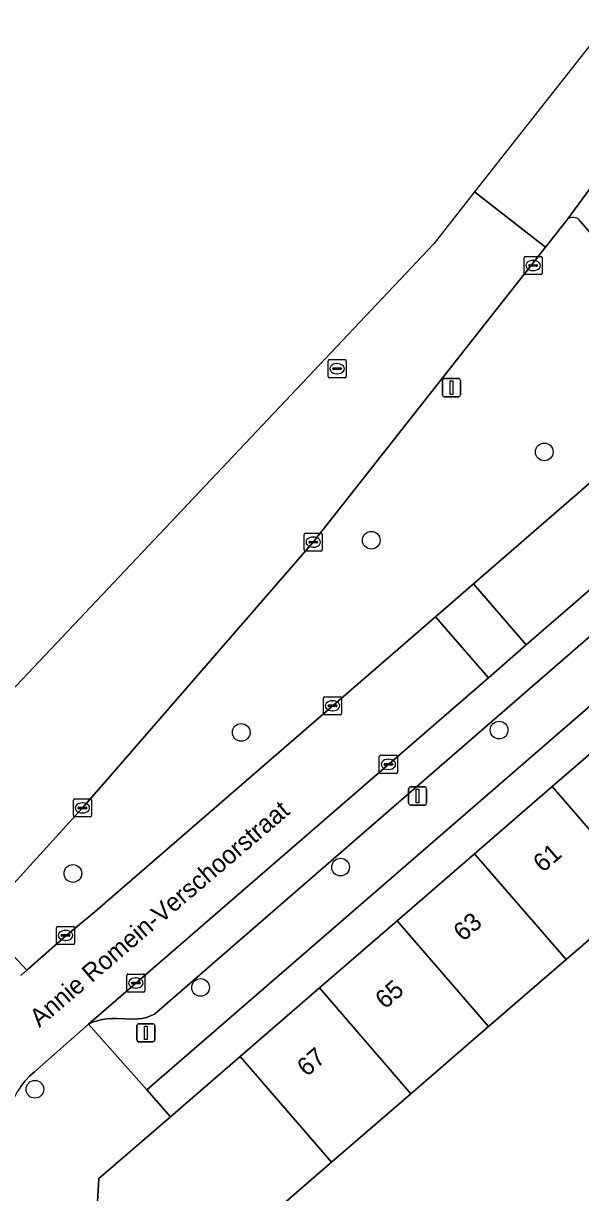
# Model space of a CAD drawing. Extents: x 160304 to 160955, y 383684 to 384161.
# Drawn here: x 160362.7 to 160393.5, y 384055.7 to 384120.3 of the extents above; entities that cross this region are included whole.
import ezdxf

# ---------------------------------------------------------------- set-up
doc = ezdxf.new("R2010")
doc.units = 0
for name, color, linetype in [('IMGEO_Berm_groen', 7, 'Continuous'), ('IMGEO_Boom', 7, 'Continuous'), ('IMGEO_Erf', 7, 'Continuous'), ('IMGEO_Kolk', 7, 'Continuous'), ('IMGEO_Lichtmast', 7, 'Continuous'), ('IMGEO_Openbare_ruimte_label', 7, 'Continuous'), ('IMGEO_Pand', 7, 'Continuous'), ('IMGEO_Pand_nummerreeks', 7, 'Continuous'), ('IMGEO_Parkeervlak_open', 7, 'Continuous'), ('IMGEO_Rijbaan_lokaal_gesloten', 7, 'Continuous'), ('IMGEO_Rijbaan_lokaal_open', 7, 'Continuous'), ('IMGEO_Rioolput', 7, 'Continuous'), ('IMGEO_Voetpad_open', 7, 'Continuous')]:
    doc.layers.add(name, color=color, linetype=linetype)

msp = doc.modelspace()

# ---------------------------------------------------------------- linework, layer by layer
at = {"layer": 'IMGEO_Berm_groen'}
for points in [[(160392.757, 384109.377), (160391.585, 384107.888), (160378.757, 384091.601), (160367.654, 384078.8), (160366.004, 384076.919), (160361.087, 384071.52), (160360.319, 384070.736), (160362.943, 384067.958), (160365.075, 384069.831), (160366.686, 384071.182), (160385.508, 384087.482)], [(160385.508, 384087.482), (160387.602, 384089.296), (160398.566, 384098.79), (160396.61, 384101.048), (160398.923, 384103.034), (160393.527, 384109.316)], [(160362.595, 384067.653), (160362.943, 384067.958), (160360.319, 384070.736), (160352.168, 384063.187), (160351.994, 384063.019), (160352.31, 384062.716), (160352.658, 384062.992), (160352.87, 384063.056)]]:
    msp.add_lwpolyline(points, dxfattribs=at)
msp.add_arc((160393.119, 384109.05), 0.487, 33.05714, 137.88375, dxfattribs=at)
at = {"layer": 'IMGEO_Boom'}
for centre in [(160391.521, 384096.582), (160381.964, 384091.704), (160374.777, 384081.092), (160389.026, 384081.218), (160365.479, 384073.297), (160380.264, 384073.648), (160372.531, 384067.002), (160363.383, 384061.375)]:
    msp.add_circle(centre, 0.489, dxfattribs=at)
at = {"layer": 'IMGEO_Erf'}
msp.add_lwpolyline([(160370.867, 384059.859), (160374.719, 384063.189), (160379.098, 384066.975), (160383.385, 384070.682), (160387.672, 384074.39), (160391.96, 384078.097), (160396.247, 384081.804), (160400.628, 384085.592), (160402.16, 384083.813), (160406.529, 384087.579), (160410.806, 384091.267), (160415.083, 384094.954), (160419.36, 384098.641), (160423.741, 384102.417), (160420.868, 384105.779), (160369.56, 384061.353)], close=True, dxfattribs=at)
msp.add_lwpolyline([(160397.013, 384072.253), (160392.724, 384068.546), (160388.436, 384064.84), (160384.148, 384061.134), (160379.769, 384057.349), (160375.75, 384053.876)], dxfattribs=at)
at = {"layer": 'IMGEO_Kolk'}
for p, q in [((160390.401, 384106.451), (160390.401, 384107.303)), ((160390.476, 384107.377), (160391.328, 384107.377)), ((160391.402, 384107.303), (160391.402, 384106.451)), ((160390.66, 384106.871), (160390.66, 384106.883)), ((160391.098, 384106.834), (160390.7, 384106.834)), ((160390.703, 384106.92), (160391.101, 384106.92)), ((160390.889, 384107.157), (160390.914, 384107.157)), ((160391.144, 384106.883), (160391.144, 384106.871)), ((160391.328, 384106.377), (160390.476, 384106.377)), ((160390.912, 384106.597), (160390.887, 384106.597)), ((160378.257, 384091.174), (160378.257, 384092.026)), ((160378.332, 384092.1), (160379.184, 384092.1)), ((160378.745, 384091.88), (160378.77, 384091.88)), ((160379.258, 384092.026), (160379.258, 384091.174)), ((160378.516, 384091.594), (160378.516, 384091.606)), ((160378.954, 384091.557), (160378.556, 384091.557)), ((160378.559, 384091.643), (160378.957, 384091.643)), ((160378.768, 384091.32), (160378.743, 384091.32)), ((160379, 384091.606), (160379, 384091.594)), ((160379.184, 384091.1), (160378.332, 384091.1)), ((160379.323, 384082.135), (160379.323, 384082.987)), ((160379.398, 384083.061), (160380.25, 384083.061)), ((160379.811, 384082.841), (160379.836, 384082.841)), ((160380.324, 384082.987), (160380.324, 384082.135)), ((160379.582, 384082.555), (160379.582, 384082.567)), ((160380.02, 384082.518), (160379.622, 384082.518)), ((160379.625, 384082.604), (160380.023, 384082.604)), ((160379.834, 384082.281), (160379.809, 384082.281)), ((160380.066, 384082.567), (160380.066, 384082.555)), ((160380.25, 384082.061), (160379.398, 384082.061)), ((160382.407, 384078.899), (160382.407, 384079.751)), ((160382.482, 384079.825), (160383.334, 384079.825)), ((160382.895, 384079.605), (160382.92, 384079.605)), ((160383.408, 384079.751), (160383.408, 384078.899)), ((160382.666, 384079.319), (160382.666, 384079.331)), ((160383.104, 384079.282), (160382.706, 384079.282)), ((160382.709, 384079.368), (160383.107, 384079.368)), ((160382.918, 384079.045), (160382.893, 384079.045)), ((160383.15, 384079.331), (160383.15, 384079.319)), ((160383.334, 384078.825), (160382.482, 384078.825)), ((160365.504, 384076.492), (160365.504, 384077.344)), ((160365.579, 384077.418), (160366.431, 384077.418)), ((160365.806, 384076.961), (160366.204, 384076.961)), ((160365.992, 384077.198), (160366.017, 384077.198)), ((160366.505, 384077.344), (160366.505, 384076.492)), ((160366.431, 384076.418), (160365.579, 384076.418)), ((160365.763, 384076.912), (160365.763, 384076.924)), ((160366.201, 384076.875), (160365.803, 384076.875)), ((160366.015, 384076.638), (160365.99, 384076.638)), ((160366.247, 384076.924), (160366.247, 384076.912)), ((160364.574, 384069.45), (160364.574, 384070.302)), ((160364.649, 384070.376), (160365.501, 384070.376)), ((160364.833, 384069.87), (160364.833, 384069.882)), ((160364.876, 384069.919), (160365.274, 384069.919)), ((160365.062, 384070.156), (160365.087, 384070.156)), ((160365.317, 384069.882), (160365.317, 384069.87)), ((160365.575, 384070.302), (160365.575, 384069.45)), ((160365.501, 384069.376), (160364.649, 384069.376)), ((160365.271, 384069.833), (160364.873, 384069.833)), ((160365.085, 384069.596), (160365.06, 384069.596)), ((160368.458, 384066.819), (160368.458, 384067.671)), ((160368.533, 384067.745), (160369.385, 384067.745)), ((160368.717, 384067.239), (160368.717, 384067.251)), ((160368.76, 384067.288), (160369.158, 384067.288)), ((160368.946, 384067.525), (160368.971, 384067.525)), ((160369.201, 384067.251), (160369.201, 384067.239)), ((160369.459, 384067.671), (160369.459, 384066.819)), ((160369.385, 384066.745), (160368.533, 384066.745)), ((160369.155, 384067.202), (160368.757, 384067.202)), ((160368.969, 384066.965), (160368.944, 384066.965))]:
    msp.add_line(p, q, dxfattribs=at)
for points in [[(160390.401, 384106.451), (160390.401, 384107.303)], [(160390.476, 384107.377), (160391.328, 384107.377)], [(160391.402, 384107.303), (160391.402, 384106.451)], [(160391.328, 384106.377), (160390.476, 384106.377)], [(160378.257, 384091.174), (160378.257, 384092.026)], [(160378.332, 384092.1), (160379.184, 384092.1)], [(160379.258, 384092.026), (160379.258, 384091.174)], [(160379.184, 384091.1), (160378.332, 384091.1)], [(160379.323, 384082.135), (160379.323, 384082.987)], [(160379.398, 384083.061), (160380.25, 384083.061)], [(160380.324, 384082.987), (160380.324, 384082.135)], [(160380.25, 384082.061), (160379.398, 384082.061)], [(160382.407, 384078.899), (160382.407, 384079.751)], [(160382.482, 384079.825), (160383.334, 384079.825)], [(160383.408, 384079.751), (160383.408, 384078.899)], [(160383.334, 384078.825), (160382.482, 384078.825)], [(160365.504, 384076.492), (160365.504, 384077.344)], [(160365.579, 384077.418), (160366.431, 384077.418)], [(160366.505, 384077.344), (160366.505, 384076.492)], [(160366.431, 384076.418), (160365.579, 384076.418)], [(160364.574, 384069.45), (160364.574, 384070.302)], [(160364.649, 384070.376), (160365.501, 384070.376)], [(160365.575, 384070.302), (160365.575, 384069.45)], [(160365.501, 384069.376), (160364.649, 384069.376)], [(160368.458, 384066.819), (160368.458, 384067.671)], [(160368.533, 384067.745), (160369.385, 384067.745)], [(160369.459, 384067.671), (160369.459, 384066.819)], [(160369.385, 384066.745), (160368.533, 384066.745)]]:
    msp.add_lwpolyline(points, dxfattribs=at)
for centre, radius, start, end in [((160390.478, 384107.301), 0.0765, 91.55205, 178.44795), ((160390.478, 384107.301), 0.0765, 91.55205, 178.44795), ((160391.326, 384107.301), 0.0765, 1.55205, 88.44795), ((160391.326, 384107.301), 0.0765, 1.55205, 88.44795), ((160390.7, 384106.88), 0.0403, 85.87752, 175.75265), ((160390.697, 384106.87), 0.0366, 178.93798, 274.71019), ((160391.101, 384106.877), 0.043, 264.86636, 352.45326), ((160391.105, 384106.882), 0.0386, 1.73085, 96.63898), ((160390.478, 384106.453), 0.0765, 181.55205, 268.44795), ((160390.478, 384106.453), 0.0765, 181.55205, 268.44795), ((160391.326, 384106.453), 0.0765, 271.55205, 358.44795), ((160391.326, 384106.453), 0.0765, 271.55205, 358.44795), ((160378.334, 384092.024), 0.0765, 91.55205, 178.44795), ((160378.334, 384092.024), 0.0765, 91.55205, 178.44795), ((160379.182, 384092.024), 0.0765, 1.55205, 88.44795), ((160379.182, 384092.024), 0.0765, 1.55205, 88.44795), ((160378.334, 384091.176), 0.0765, 181.55205, 268.44795), ((160378.334, 384091.176), 0.0765, 181.55205, 268.44795), ((160378.556, 384091.603), 0.0403, 85.87752, 175.75265), ((160378.553, 384091.593), 0.0366, 178.93798, 274.71019), ((160378.957, 384091.6), 0.043, 264.86636, 352.45326), ((160378.961, 384091.605), 0.0386, 1.73085, 96.63898), ((160379.182, 384091.176), 0.0765, 271.55205, 358.44795), ((160379.182, 384091.176), 0.0765, 271.55205, 358.44795), ((160379.4, 384082.985), 0.0765, 91.55205, 178.44795), ((160379.4, 384082.985), 0.0765, 91.55205, 178.44795), ((160380.248, 384082.985), 0.0765, 1.55205, 88.44795), ((160380.248, 384082.985), 0.0765, 1.55205, 88.44795), ((160379.4, 384082.137), 0.0765, 181.55205, 268.44795), ((160379.4, 384082.137), 0.0765, 181.55205, 268.44795), ((160379.622, 384082.564), 0.0403, 85.87752, 175.75265), ((160379.619, 384082.554), 0.0366, 178.93798, 274.71019), ((160380.023, 384082.561), 0.043, 264.86636, 352.45326), ((160380.027, 384082.566), 0.0386, 1.73085, 96.63898), ((160380.248, 384082.137), 0.0765, 271.55205, 358.44795), ((160380.248, 384082.137), 0.0765, 271.55205, 358.44795), ((160382.484, 384079.749), 0.0765, 91.55205, 178.44795), ((160382.484, 384079.749), 0.0765, 91.55205, 178.44795), ((160383.332, 384079.749), 0.0765, 1.55205, 88.44795), ((160383.332, 384079.749), 0.0765, 1.55205, 88.44795), ((160382.484, 384078.901), 0.0765, 181.55205, 268.44795), ((160382.484, 384078.901), 0.0765, 181.55205, 268.44795), ((160382.706, 384079.328), 0.0403, 85.87752, 175.75265), ((160382.703, 384079.318), 0.0366, 178.93798, 274.71019), ((160383.107, 384079.325), 0.043, 264.86636, 352.45326), ((160383.111, 384079.33), 0.0386, 1.73085, 96.63898), ((160383.332, 384078.901), 0.0765, 271.55205, 358.44795), ((160383.332, 384078.901), 0.0765, 271.55205, 358.44795), ((160365.581, 384077.342), 0.0765, 91.55205, 178.44795), ((160365.581, 384077.342), 0.0765, 91.55205, 178.44795), ((160365.803, 384076.921), 0.0403, 85.87752, 175.75265), ((160366.208, 384076.923), 0.0386, 1.73085, 96.63898), ((160366.429, 384077.342), 0.0765, 1.55205, 88.44795), ((160366.429, 384077.342), 0.0765, 1.55205, 88.44795), ((160365.581, 384076.494), 0.0765, 181.55205, 268.44795), ((160365.581, 384076.494), 0.0765, 181.55205, 268.44795), ((160365.8, 384076.911), 0.0366, 178.93798, 274.71019), ((160366.204, 384076.918), 0.043, 264.86636, 352.45326), ((160366.429, 384076.494), 0.0765, 271.55205, 358.44795), ((160366.429, 384076.494), 0.0765, 271.55205, 358.44795), ((160364.651, 384070.3), 0.0765, 91.55205, 178.44795), ((160364.651, 384070.3), 0.0765, 91.55205, 178.44795), ((160364.873, 384069.879), 0.0403, 85.87752, 175.75265), ((160364.87, 384069.869), 0.0366, 178.93798, 274.71019), ((160365.274, 384069.876), 0.043, 264.86636, 352.45326), ((160365.278, 384069.881), 0.0386, 1.73085, 96.63898), ((160365.499, 384070.3), 0.0765, 1.55205, 88.44795), ((160365.499, 384070.3), 0.0765, 1.55205, 88.44795), ((160364.651, 384069.452), 0.0765, 181.55205, 268.44795), ((160364.651, 384069.452), 0.0765, 181.55205, 268.44795), ((160365.499, 384069.452), 0.0765, 271.55205, 358.44795), ((160365.499, 384069.452), 0.0765, 271.55205, 358.44795), ((160368.535, 384067.669), 0.0765, 91.55205, 178.44795), ((160368.535, 384067.669), 0.0765, 91.55205, 178.44795), ((160368.757, 384067.248), 0.0403, 85.87752, 175.75265), ((160369.162, 384067.25), 0.0386, 1.73085, 96.63898), ((160369.383, 384067.669), 0.0765, 1.55205, 88.44795), ((160369.383, 384067.669), 0.0765, 1.55205, 88.44795), ((160368.535, 384066.821), 0.0765, 181.55205, 268.44795), ((160368.535, 384066.821), 0.0765, 181.55205, 268.44795), ((160368.754, 384067.238), 0.0366, 178.93798, 274.71019), ((160369.158, 384067.245), 0.043, 264.86636, 352.45326), ((160369.383, 384066.821), 0.0765, 271.55205, 358.44795), ((160369.383, 384066.821), 0.0765, 271.55205, 358.44795)]:
    msp.add_arc(centre, radius, start, end, dxfattribs=at)
for centre, major_axis, ratio, start_param, end_param in [((160390.888, 384106.877), (-0.387, 0.002), 0.722429, 4.712389, 7.853982), ((160390.913, 384106.877), (-0.39, 0.002), 0.717154, 1.570796, 4.712389), ((160378.744, 384091.6), (-0.387, 0.002), 0.722429, 4.712389, 7.853982), ((160378.769, 384091.6), (-0.39, 0.002), 0.717154, 1.570796, 4.712389), ((160379.81, 384082.561), (-0.387, 0.002), 0.722429, 4.712389, 7.853982), ((160379.835, 384082.561), (-0.39, 0.002), 0.717154, 1.570796, 4.712389), ((160382.894, 384079.325), (-0.387, 0.002), 0.722429, 4.712389, 7.853982), ((160382.919, 384079.325), (-0.39, 0.002), 0.717154, 1.570796, 4.712389), ((160365.991, 384076.918), (-0.387, 0.002), 0.722429, 4.712389, 7.853982), ((160366.016, 384076.918), (-0.39, 0.002), 0.717154, 1.570796, 4.712389), ((160365.061, 384069.876), (-0.387, 0.002), 0.722429, 4.712389, 7.853982), ((160365.086, 384069.876), (-0.39, 0.002), 0.717154, 1.570796, 4.712389), ((160368.945, 384067.245), (-0.387, 0.002), 0.722429, 4.712389, 7.853982), ((160368.97, 384067.245), (-0.39, 0.002), 0.717154, 1.570796, 4.712389)]:
    msp.add_ellipse(centre, major_axis=major_axis, ratio=ratio, start_param=start_param, end_param=end_param, dxfattribs=at)
at = {"layer": 'IMGEO_Lichtmast'}
for p, q in [((160385.895, 384099.733), (160385.895, 384100.533)), ((160385.895, 384100.533), (160385.895, 384099.733)), ((160385.995, 384100.633), (160386.785, 384100.633)), ((160386.785, 384100.633), (160385.995, 384100.633)), ((160386.885, 384100.533), (160386.885, 384099.733)), ((160386.885, 384099.733), (160386.885, 384100.533)), ((160386.785, 384099.633), (160385.995, 384099.633)), ((160385.995, 384099.633), (160386.785, 384099.633)), ((160384.025, 384077.175), (160384.025, 384077.975)), ((160384.025, 384077.975), (160384.025, 384077.175)), ((160384.125, 384078.075), (160384.915, 384078.075)), ((160384.915, 384078.075), (160384.125, 384078.075)), ((160385.015, 384077.975), (160385.015, 384077.175)), ((160385.015, 384077.175), (160385.015, 384077.975)), ((160384.915, 384077.075), (160384.125, 384077.075)), ((160384.125, 384077.075), (160384.915, 384077.075)), ((160369.012, 384064.097), (160369.012, 384064.897)), ((160369.012, 384064.897), (160369.012, 384064.097)), ((160369.112, 384064.997), (160369.902, 384064.997)), ((160369.902, 384064.997), (160369.112, 384064.997)), ((160370.002, 384064.897), (160370.002, 384064.097)), ((160370.002, 384064.097), (160370.002, 384064.897)), ((160369.902, 384063.997), (160369.112, 384063.997)), ((160369.112, 384063.997), (160369.902, 384063.997))]:
    msp.add_line(p, q, dxfattribs=at)
for points in [[(160386.315, 384100.508), (160386.465, 384100.508), (160386.465, 384099.758), (160386.315, 384099.758), (160386.315, 384100.508)], [(160384.445, 384077.95), (160384.595, 384077.95), (160384.595, 384077.2), (160384.445, 384077.2), (160384.445, 384077.95)], [(160369.432, 384064.872), (160369.582, 384064.872), (160369.582, 384064.122), (160369.432, 384064.122), (160369.432, 384064.872)]]:
    msp.add_lwpolyline(points, dxfattribs=at)
for centre, start, end in [((160385.995, 384100.533), 90, 180), ((160385.995, 384100.533), 90, 180), ((160386.785, 384100.533), 0, 90), ((160386.785, 384100.533), 360, 90), ((160385.995, 384099.733), 180, 270), ((160385.995, 384099.733), 180, 270), ((160386.785, 384099.733), 270, 0), ((160386.785, 384099.733), 270, 0), ((160384.125, 384077.975), 90, 180), ((160384.125, 384077.975), 90, 180), ((160384.915, 384077.975), 0, 90), ((160384.915, 384077.975), 360, 90), ((160384.125, 384077.175), 180, 270), ((160384.125, 384077.175), 180, 270), ((160384.915, 384077.175), 270, 0), ((160384.915, 384077.175), 270, 0), ((160369.112, 384064.897), 90, 180), ((160369.112, 384064.897), 90, 180), ((160369.902, 384064.897), 0, 90), ((160369.902, 384064.897), 360, 90), ((160369.112, 384064.097), 180, 270), ((160369.112, 384064.097), 180, 270), ((160369.902, 384064.097), 270, 0), ((160369.902, 384064.097), 270, 0)]:
    msp.add_arc(centre, 0.1, start, end, dxfattribs=at)
at = {"layer": 'IMGEO_Pand'}
for points in [[(160391.96, 384078.097), (160397.013, 384072.253), (160401.301, 384075.959), (160396.247, 384081.804)], [(160391.96, 384078.097), (160387.672, 384074.39), (160392.724, 384068.546), (160397.013, 384072.253)], [(160383.385, 384070.682), (160388.436, 384064.84), (160392.724, 384068.546), (160387.672, 384074.39)], [(160379.098, 384066.975), (160384.148, 384061.134), (160388.436, 384064.84), (160383.385, 384070.682)], [(160379.098, 384066.975), (160374.719, 384063.189), (160379.769, 384057.349), (160384.148, 384061.134)], [(160379.769, 384057.349), (160374.719, 384063.189), (160370.867, 384059.859), (160366.918, 384056.444), (160366.832, 384055.157), (160366.712, 384053.361), (160366.625, 384052.063), (160369.22, 384049.062), (160373.455, 384044.164), (160379.304, 384049.215), (160375.721, 384053.359), (160375.75, 384053.876)]]:
    msp.add_lwpolyline(points, close=True, dxfattribs=at)
at = {"layer": 'IMGEO_Parkeervlak_open'}
msp.add_lwpolyline([(160399.384, 384093.594), (160390.525, 384085.922), (160388.431, 384084.109), (160366.337, 384064.976), (160366.57, 384065.079), (160366.829, 384065.167), (160367.094, 384065.232), (160367.365, 384065.273), (160367.638, 384065.29), (160367.912, 384065.282), (160368.819, 384065.249), (160369.062, 384065.261), (160369.302, 384065.296), (160369.539, 384065.351), (160369.77, 384065.428), (160369.98, 384065.518), (160413.547, 384103.317)], dxfattribs=at)
at = {"layer": 'IMGEO_Rijbaan_lokaal_gesloten'}
msp.add_lwpolyline([(160394.994, 384120.252), (160387.672, 384110.946), (160391.585, 384107.888), (160392.757, 384109.377), (160395.112, 384112.569), (160397.736, 384115.959), (160398.679, 384117.35)], close=True, dxfattribs=at)
for points in [[(160387.672, 384110.946), (160385.413, 384108.074), (160347.496, 384067.978), (160304.005, 384030.821)], [(160327.338, 384042.569), (160343.612, 384055.892), (160351.994, 384063.019), (160352.168, 384063.187), (160360.319, 384070.736), (160361.087, 384071.52), (160366.004, 384076.919), (160367.654, 384078.8), (160378.757, 384091.601), (160391.585, 384107.888), (160387.672, 384110.946)]]:
    msp.add_lwpolyline(points, dxfattribs=at)
at = {"layer": 'IMGEO_Rijbaan_lokaal_open'}
for points in [[(160412.264, 384110.636), (160403.163, 384102.78), (160400.861, 384100.778), (160398.566, 384098.79), (160387.602, 384089.296), (160390.525, 384085.922), (160399.384, 384093.594), (160414.316, 384106.549)], [(160362.604, 384061.536), (160362.831, 384061.826), (160363.083, 384062.094), (160363.357, 384062.338), (160366.337, 384064.976), (160388.431, 384084.109), (160385.508, 384087.482), (160366.686, 384071.182), (160365.075, 384069.831), (160362.943, 384067.958), (160362.595, 384067.653)]]:
    msp.add_lwpolyline(points, dxfattribs=at)
msp.add_lwpolyline([(160388.431, 384084.109), (160390.525, 384085.922), (160387.602, 384089.296), (160385.508, 384087.482)], close=True, dxfattribs=at)
at = {"layer": 'IMGEO_Rioolput'}
for p, q in [((160379.574, 384100.752), (160379.574, 384101.604)), ((160379.649, 384101.678), (160380.501, 384101.678)), ((160380.575, 384101.604), (160380.575, 384100.752)), ((160379.833, 384101.172), (160379.833, 384101.184)), ((160380.271, 384101.135), (160379.873, 384101.135)), ((160379.876, 384101.221), (160380.274, 384101.221)), ((160380.085, 384100.898), (160380.06, 384100.898)), ((160380.062, 384101.458), (160380.087, 384101.458)), ((160380.317, 384101.184), (160380.317, 384101.172)), ((160380.501, 384100.678), (160379.649, 384100.678))]:
    msp.add_line(p, q, dxfattribs=at)
for points in [[(160379.574, 384100.752), (160379.574, 384101.604)], [(160379.649, 384101.678), (160380.501, 384101.678)], [(160380.575, 384101.604), (160380.575, 384100.752)], [(160380.501, 384100.678), (160379.649, 384100.678)]]:
    msp.add_lwpolyline(points, dxfattribs=at)
for centre, radius, start, end in [((160379.651, 384101.602), 0.0765, 91.55205, 178.44795), ((160379.651, 384101.602), 0.0765, 91.55205, 178.44795), ((160380.499, 384101.602), 0.0765, 1.55205, 88.44795), ((160380.499, 384101.602), 0.0765, 1.55205, 88.44795), ((160379.873, 384101.181), 0.0403, 85.87752, 175.75265), ((160379.87, 384101.171), 0.0366, 178.93798, 274.71019), ((160380.274, 384101.178), 0.043, 264.86636, 352.45326), ((160380.278, 384101.183), 0.0386, 1.73085, 96.63898), ((160379.651, 384100.754), 0.0765, 181.55205, 268.44795), ((160379.651, 384100.754), 0.0765, 181.55205, 268.44795), ((160380.499, 384100.754), 0.0765, 271.55205, 358.44795), ((160380.499, 384100.754), 0.0765, 271.55205, 358.44795)]:
    msp.add_arc(centre, radius, start, end, dxfattribs=at)
for centre, major_axis, ratio, start_param, end_param in [((160380.061, 384101.178), (-0.387, 0.002), 0.722429, 4.712389, 7.853982), ((160380.086, 384101.178), (-0.39, 0.002), 0.717154, 1.570796, 4.712389)]:
    msp.add_ellipse(centre, major_axis=major_axis, ratio=ratio, start_param=start_param, end_param=end_param, dxfattribs=at)
at = {"layer": 'IMGEO_Voetpad_open'}
for points in [[(160395.112, 384112.569), (160392.757, 384109.377)], [(160393.527, 384109.316), (160398.923, 384103.034), (160400.861, 384100.778), (160403.163, 384102.78), (160395.225, 384111.986)], [(160413.547, 384103.317), (160369.98, 384065.518), (160369.77, 384065.428), (160369.539, 384065.351), (160369.302, 384065.296), (160369.062, 384065.261), (160368.819, 384065.249), (160367.912, 384065.282), (160367.638, 384065.29), (160367.365, 384065.273), (160367.094, 384065.232), (160366.829, 384065.167), (160366.57, 384065.079), (160366.337, 384064.976), (160369.56, 384061.353), (160420.868, 384105.779)], [(160366.832, 384055.157), (160366.918, 384056.444), (160370.867, 384059.859), (160369.56, 384061.353), (160366.337, 384064.976), (160363.357, 384062.338), (160363.083, 384062.094), (160362.831, 384061.826), (160362.604, 384061.536), (160362.405, 384061.228), (160362.233, 384060.903), (160362.091, 384060.564), (160361.981, 384060.214), (160361.901, 384059.855), (160361.866, 384059.607), (160361.837, 384059.349), (160361.366, 384053.113)]]:
    msp.add_lwpolyline(points, dxfattribs=at)
msp.add_arc((160393.119, 384109.05), 0.487, 33.05714, 137.88375, dxfattribs=at)

# ---------------------------------------------------------------- texts
at = {"layer": 'IMGEO_Openbare_ruimte_label'}
msp.add_text('Annie Romein-Verschoorstraat', height=1, rotation=40.49558, dxfattribs=at).set_placement((160363.627, 384064.764))
at = {"layer": 'IMGEO_Pand_nummerreeks'}
for s, p in [('61', (160391.439, 384073.309)), ('63', (160387.036, 384069.501)), ('65', (160382.718, 384065.767)), ('67', (160378.4, 384062.033))]:
    msp.add_text(s, height=1, rotation=40.85189, dxfattribs=at).set_placement(p)

doc.saveas('drawing.dxf')
